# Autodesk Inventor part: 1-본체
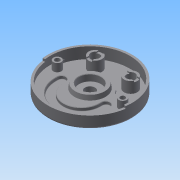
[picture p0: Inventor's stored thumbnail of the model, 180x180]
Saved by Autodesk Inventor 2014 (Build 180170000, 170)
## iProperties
Created: 2015-06
Part Number: 1-본체
Material: Generic
Document SubType Name: Modeling
Designer: Administrator
Density: 1 g/cm^3
Appearance: Default
Author: Administrator
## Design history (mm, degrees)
sketch "스케치1"
  geometry: C1 r 95 at (0, 0); 1 further point
  constraints: 1 centre point, 1 coincident
  dimensions: "d0" = 190 diameter of C1
extrude "돌출1" new body sketch "스케치1" distance "d1" = 32; taper "d2" = 0 deg
sketch "스케치2"
  geometry: C1 r 95 at (0, 0) reference; C2 r 90 at (0, 0)
  constraints: 1 centre point, 1 coincident
  dimensions: "d3" = 180 diameter of C2
extrude "돌출2" cut sketch "스케치2" distance "d4" = 18; taper "d5" = 0 deg
sketch "스케치3"
  geometry: L1 (-38.833, 16)-(-88.566, 16); L2 (38.833, 16)-(88.566, 16); A1 r 90 centre (0, 0) between (-88.566, 16) and (88.566, 16) reference; A2 r 42 centre (0, 0) between (38.833, 16) and (-38.833, 16)
  constraints: 4 end point, 4 point on circle, 2 collinear, 1 centre point, 1 coincident, 1 horizontal
  dimensions: "d6" = 84 diameter of A2; "d7" = 16 distance from line of A1.centre L1
extrude "돌출3" cut sketch "스케치3" distance "d8" = 7; taper "d9" = 0 deg
sketch "스케치4"
  geometry: C1 r 35 at (0, 0); A1 r 42 centre (0, 0) between (38.833, 16) and (-38.833, 16) reference
  constraints: 1 centre point, 1 coincident
  dimensions: "d10" = 70 diameter of C1
extrude "돌출4" join sketch "스케치4" distance "d11" = 10; taper "d12" = -10 deg
sketch "스케치5"
  geometry: L1 (-95, 0)-(95, 0); L2 (0, 0)-(-94.075, -13.221); L3 (0, 0)-(94.075, -13.221); C1 r 90 at (0, 0) reference; A1 r 95 centre (0, 0) between (-95, 0) and (95, 0) reference
  constraints: 6 end point, 4 point on circle, 1 coincident, 1 horizontal, 1 midpoint
  dimensions: "d13" = 8 deg angle of L1 L2; "d14" = 8 deg angle of L3 L1
extrude "돌출5" cut sketch "스케치5" distance "d15" = 5; taper "d16" = 0 deg
sketch "스케치6"
  geometry: L1 (88.566, 16)-(38.833, 16) reference; L2 (-74, 0)-(74, 0); C1 r 35 at (0, 0) reference; C2 r 9 at (-74, 0); C3 r 9 at (74, 0); 1 further point
  constraints: 3 coincident, 2 centre point, 2 end point, 1 midpoint, 1 parallel
  dimensions: "d17" = 148 distance of L2.start L2.end; "d18" = 18 diameter of C2; "d19" = 18 diameter of C3
extrude "돌출6" join sketch "스케치6" stored distance "d20" = 5; taper "d21" = 0 deg
sketch "스케치7"
  geometry: L1 (88.566, 16)-(38.833, 16) reference; L2 (-87.972, -19)-(87.972, -19); L3 (-88.904, -14)-(88.904, -14); L4 (-59, -19)-(-59, -16.477); L5 (-59, -16.477)-(-59, -14); L6 (-41, -19)-(-41, -14); L7 (41, -19)-(41, -14); L8 (59, -19)-(59, -14); C1 r 35 at (0, 0) reference; A1 r 90 centre (0, 0) between (-88.566, 16) and (88.566, 16) reference; A2 r 59 centre (0, -19) between (-59, -19) and (59, -19); A3 r 41 centre (0, -19) between (-41, -19) and (41, -19); A4 r 9 centre (-50, -14) between (-41, -14) and (-59, -14); A5 r 9 centre (50, -14) between (59, -14) and (41, -14)
  constraints: 14 end point, 12 point on circle, 8 point on line, 8 tangent, 4 centre point, 4 perpendicular, 2 parallel, 1 coincident, 1 midpoint, 1 vertical alignment
  dimensions: "d22" = 19 distance of A2.centre C1.centre; "d23" = 118 diameter of A2; "d24" = 82 diameter of A3; "d25" = 5 distance between parallel lines of L3 L2
extrude "돌출7" cut sketch "스케치7" distance "d26" = 7; taper "d27" = 0 deg
sketch "스케치8"
  geometry: L1 (-38.833, 16)-(-88.566, 16) reference; L2 (-40, 52)-(40, 52); C1 r 15 at (-40, 52); C2 r 15 at (40, 52); A1 r 42 centre (0, 0) between (38.833, 16) and (-38.833, 16) reference; 1 further point
  constraints: 2 centre point, 2 coincident, 2 end point, 1 midpoint, 1 parallel, 1 vertical alignment
  dimensions: "d28" = 52 distance of A1.centre point (0, 52); "d29" = 80 distance of L2.start L2.end; "d30" = 30 diameter of C1; "d31" = 30 diameter of C2
extrude "돌출8" join sketch "스케치8" stored distance "d32" = 7; taper "d33" = 0 deg
sketch "스케치9"
  geometry: C1 r 95 at (0, 0) reference; C2 r 26 at (0, 0)
  constraints: 1 centre point, 1 coincident
  dimensions: "d34" = 52 diameter of C2
extrude "돌출9" join sketch "스케치9" distance "d35" = 12; taper "d36" = -15 deg
hole "구멍1" diameter "d39" = 23; stored, may be unused: countersink angle "d43" = 90 deg, drill point angle "d45" = 118 deg; dims "d37" = 10, "d38" = 10, "d40" = 6, "d41" = 50, "d42" = 15, "d44" = 8
sketch "스케치10"
  geometry: C1 r 15 at (0, 0) reference; C2 r 15 at (80, 0) reference; 3 further points
  constraints: 2 coincident
hole "구멍2" sketch "스케치10" at (0, 0), (80, 0) diameter "d46" = 20; stored, may be unused: countersink angle "d50" = 90 deg, drill point angle "d52" = 118 deg; dims "d47" = 6, "d48" = 50, "d49" = 15, "d51" = 8
sketch "스케치11"
  geometry: C1 r 10 at (40, 52) reference; C2 r 10 at (-40, 52) reference; C3 r 26 at (0, 0) reference; C4 r 95 at (0, 0) reference; C5 r 9 at (-74, 0) reference; C6 r 9 at (74, 0) reference; 2 further points
  constraints: 2 coincident
hole "구멍3" sketch "스케치11" at (-74, 0), (74, 0) diameter "d53" = 11; stored, may be unused: countersink angle "d57" = 90 deg, drill point angle "d59" = 118 deg; dims "d54" = 6, "d55" = 18, "d56" = 11, "d58" = 8
sketch "스케치12"
  geometry: C1 r 95 at (0, 0) reference; C2 r 68 at (0, 0)
  constraints: 1 centre point, 1 coincident, 1 other
  dimensions: "d60" = 136 diameter of C2
feature "엠보싱1" sketch "스케치12" dims "d61" = 0.5, "d62" = 0
sketch "스케치13"
  geometry: L1 (-6, 13.748)-(-6, -13.748); L2 (6, 13.748)-(6, -13.748); L3 (66.252, 6)-(93.748, 6); L4 (66.252, -6)-(93.748, -6); C1 r 10 at (80, 0) reference; A1 r 15 centre (0, 0) between (-6, 13.748) and (-6, -13.748) reference; A2 r 15 centre (80, 0) between (66.252, 6) and (93.748, 6) reference; 1 further point
  constraints: 8 end point, 8 point on circle, 4 parallel, 1 perpendicular, 1 vertical
  dimensions: "d63" = 12 distance from line of L2.start L1; "d64" = 12 distance between parallel lines of L4 L3
extrude "돌출10" cut sketch "스케치13" distance "d65" = 3; taper "d66" = 0 deg
chamfer "모따기1" distance "d67" = 1; stored, may be unused: second distance "d68" = 2, angle "d69" = 45 deg
fillet "모깎기1" dims "d70" = 10, "d71" = 0.3, "d72" = 1, "d73" = 5
node "솔리드1"
node "투영된 루프1"
node "투영된 루프2"
node "투영된 루프3"
